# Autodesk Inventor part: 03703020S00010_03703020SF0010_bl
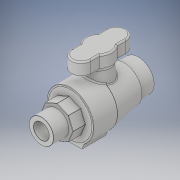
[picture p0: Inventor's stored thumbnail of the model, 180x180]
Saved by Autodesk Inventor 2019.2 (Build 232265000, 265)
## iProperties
Created: 2022-04
Part Number: 03703020S00010_03703020SF0010_bl
Material: Generic
Description: PA Ball Valve Female 1'' x Male 1''
Document SubType Name: Modeling
Designer: Lenora
Density: 1 g/cm^3
Appearance: Default
Author: Lenora
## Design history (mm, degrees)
derived "0370302.ipt"
feature "Solid1::0370302.ipt" dims "ScaleForDerivedMember" = 10
tag "TaggingFeature1"
body "Solid1"
other parameters: "d0" = 133 [user parameter], "d1" = 21 [user parameter], "d2" = 22 [user parameter], "d3" = 2.2 [user parameter], "d4" = 33.249 [user parameter], "d8" = 30.291 [user parameter], "d9" = 41 [user parameter], "d10" = 100 deg [user parameter], "d11" = 25 [user parameter], "d12" = 16.8 [user parameter], "d14" = 21.45 [user parameter], "d15" = 24.75 [user parameter], "d16" = 54.53 [user parameter], "d17" = 21.25 [user parameter], "d18" = 25 [user parameter], "d19" = 1 [user parameter], "d20" = 33.25 [user parameter], "d21" = 64 [user parameter], "d22" = 85 deg [user parameter], "d23" = 19.2 [user parameter], "d24" = 35.91 [user parameter], "d25" = 1 [user parameter], "d26" = 16.625 [user parameter], "d27" = 64 [user parameter], "d34" = 23.94 [user parameter], "d35" = 13.3 [user parameter], "d37" = 0 [user parameter], "d39" = 360 deg [user parameter], "d41" = 59.52 [user parameter], "d42" = 80 deg [user parameter], "d43" = 33 [user parameter], "d44" = 32 [user parameter], "d45" = 70 deg [user parameter], "d46" = 70 deg [user parameter], "d48" = 0 [user parameter], "d50" = 0 [user parameter], "d51" = 0.5 [user parameter], "d52" = 0.25 [user parameter], "d55" = 2 [user parameter], "d56" = 2 [user parameter], "d57" = 2 [user parameter], "Rc" = 30.291 [user parameter], "R" = 33.249 [user parameter], "DN" = 25 [user parameter], "A1" = 33 [user parameter], "A2" = 64 [user parameter], "H_" = 133 [user parameter], "l1" = 22 [user parameter], "l2" = 21 [user parameter], "B" = 41 [user parameter], "E_" = 64 [user parameter]
